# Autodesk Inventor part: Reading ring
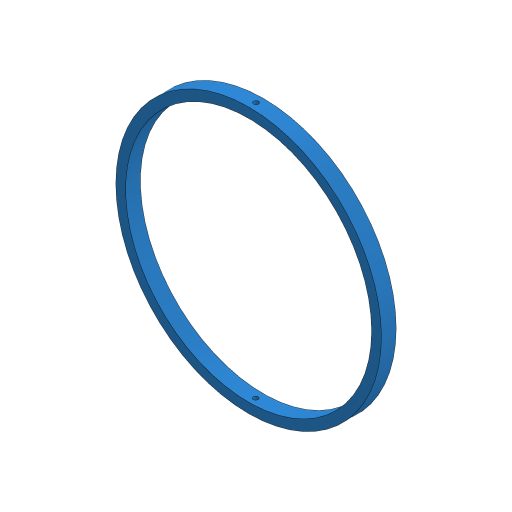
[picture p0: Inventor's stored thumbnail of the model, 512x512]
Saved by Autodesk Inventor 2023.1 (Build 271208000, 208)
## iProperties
Created: 2020-01
Part Number: Reading ring
Material: Generic
Document SubType Name: Modeling
Designer: ftrauzettel
Density: 1 g/cm^3
Appearance: Default
Sending System: SolidWorks 2016
Last Author: Pam
Last Saved: 2020-02-20
Author: ftrauzettel
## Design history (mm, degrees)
feature "Cut-Extrude2"
body "Solid1"
